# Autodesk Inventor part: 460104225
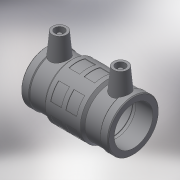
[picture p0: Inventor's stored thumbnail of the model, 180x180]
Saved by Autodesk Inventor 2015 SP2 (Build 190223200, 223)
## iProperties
Created: 2017-06
Part Number: 460104225
Material: Generic
Description: PLASSON LIGHTFIT COUPLER 225
Document SubType Name: Modeling
Designer: KIM
Mass: 89.5427 g
Surface Area: 304.58 cm^2
Volume: 89.5427 cm^3
Density: 1 g/cm^3
Appearance: Default
Author: KIM
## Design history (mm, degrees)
derived "460104.ipt"
feature "Solid1::460104.ipt"
tag "TaggingFeature1"
body "Solid1"
other parameters: "d14" = 17.6296, "d15" = 118, "d16" = 118, "d17" = 222.75, "d18" = 225, "d19" = 3.52592, "d20" = 168 deg, "d22" = 248.16, "d23" = 264, "d24" = 240.7152, "d25" = 135 deg, "d26" = 96, "d27" = 135 deg, "d29" = 141, "d35" = 15, "d39" = 5 deg, "d44" = 4, "d46" = 14, "d47" = 0, "d52" = 258.72, "d53" = 12, "d54" = 12, "d55" = 12, "d56" = 35 deg, "d58" = 360 deg, "d60" = 23.6, "d61" = 135 deg, "d62" = 108, "d63" = 3, "d64" = 0, "d_" = 225, "L_1" = 118, "D_" = 264, "A_" = 141, "d_2" = 12
